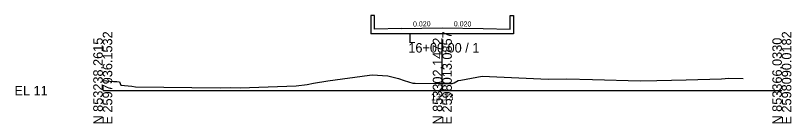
# Model space of a CAD drawing. Extents: x -26 to 1203, y -10 to 9526.
# Drawn here: x -25.7 to 202.8, y 5990.3 to 6022.1 of the extents above; entities that cross this region are included whole.
import ezdxf

# ---------------------------------------------------------------- set-up
doc = ezdxf.new("R2010")
doc.units = 0
for name, color, linetype in [('Exist Cross Section Cell', 7, 'Continuous'), ('Exist XS Center Line Elevation Label', 7, 'Continuous'), ('Exist XS Ground Line', 7, 'Continuous'), ('Prop XS Bridge', 7, 'Continuous'), ('Prop XS SE Text', 7, 'Continuous')]:
    doc.layers.add(name, color=color, linetype=linetype)

msp = doc.modelspace()

# ---------------------------------------------------------------- linework, layer by layer
at = {"layer": 'Exist Cross Section Cell'}
for p, q in [((100, 6000), (100, 6014.03)), ((0, 6000), (100, 6000)), ((100, 6000), (200, 6000))]:
    msp.add_line(p, q, dxfattribs=at)
at = {"layer": 'Exist XS Ground Line'}
for p, q in [((66.33, 6002.86), (78.52, 6004.55)), ((78.52, 6004.55), (79.36, 6004.68)), ((79.36, 6004.68), (83.95, 6004.32)), ((83.95, 6004.32), (87.07, 6003.61)), ((87.07, 6003.61), (88.76, 6002.98)), ((105.49, 6003.13), (111.77, 6004.24)), ((111.77, 6004.24), (131.17, 6003.38)), ((182.22, 6003.52), (184.41, 6003.63)), ((184.41, 6003.63), (188.62, 6003.6)), ((0, 6003), (3.19, 6002.67)), ((3.19, 6002.67), (4.13, 6002.68)), ((4.13, 6002.68), (4.96, 6002.63)), ((4.96, 6002.63), (5.31, 6001.6)), ((5.31, 6001.6), (8.56, 6001.28)), ((8.56, 6001.28), (9.61, 6001.08)), ((40.44, 6000.81), (56.94, 6001.42)), ((56.94, 6001.42), (60.17, 6001.85)), ((60.17, 6001.85), (62.04, 6002.18)), ((62.04, 6002.18), (66.33, 6002.86)), ((88.76, 6002.98), (91.36, 6002.23)), ((91.36, 6002.23), (91.97, 6002.19)), ((91.97, 6002.19), (100, 6002.13)), ((100, 6002.13), (102.86, 6002.11)), ((102.86, 6002.11), (103.48, 6002.31)), ((103.48, 6002.31), (104.63, 6002.95)), ((104.63, 6002.95), (105.49, 6003.13)), ((131.17, 6003.38), (136.65, 6003.44)), ((136.65, 6003.44), (144.27, 6003.31)), ((144.27, 6003.31), (158.31, 6002.9)), ((158.31, 6002.9), (163.15, 6002.99)), ((163.15, 6002.99), (171.79, 6003.19)), ((171.79, 6003.19), (182.22, 6003.52)), ((9.61, 6001.08), (34.56, 6000.86)), ((34.56, 6000.86), (37.66, 6000.91)), ((37.66, 6000.91), (40.44, 6000.81))]:
    msp.add_line(p, q, dxfattribs=at)
at = {"layer": 'Prop XS Bridge'}
for p, q in [((79, 6022.15), (79, 6018.15)), ((80, 6022.15), (79, 6022.15)), ((80, 6018.15), (80, 6022.15)), ((120, 6018.15), (120, 6022.15)), ((120, 6022.15), (121, 6022.15)), ((121, 6022.15), (121, 6016.73)), ((79, 6018.15), (79, 6016.73)), ((88, 6018.31), (80, 6018.15)), ((88, 6018.31), (100, 6018.55)), ((100, 6018.55), (112, 6018.31)), ((112, 6018.31), (120, 6018.15)), ((121, 6016.73), (79, 6016.73))]:
    msp.add_line(p, q, dxfattribs=at)

# ---------------------------------------------------------------- texts
at = {"layer": 'Exist Cross Section Cell'}
for s, p in [('E 2597936.1532', (2.8, 5990)), ('E 2598013.0857', (102.8, 5990)), ('E 2598090.0182', (202.8, 5990)), ('N 853238.2615', (0, 5990)), ('N 853302.1472', (100, 5990)), ('N 853366.0330', (200, 5990))]:
    msp.add_text(s, height=2.8, rotation=90, dxfattribs=at).set_placement(p)
for s, p in [('L', (90, 6014.03)), ('16+00.00 / 1', (90, 6011.23)), ('EL 11', (-26, 5998.6))]:
    msp.add_text(s, height=2.8, dxfattribs=at).set_placement(p)
at = {"layer": 'Exist XS Center Line Elevation Label'}
msp.add_text('13.13', height=2, dxfattribs=at).set_placement((96.62, 5997.13))
at = {"layer": 'Prop XS SE Text'}
for rotation, p in [(1.1458, (91.38, 6018.88)), (358.8542, (103.38, 6018.98))]:
    msp.add_text('0.020', height=1.5, rotation=rotation, dxfattribs=at).set_placement(p)

doc.saveas('drawing.dxf')
